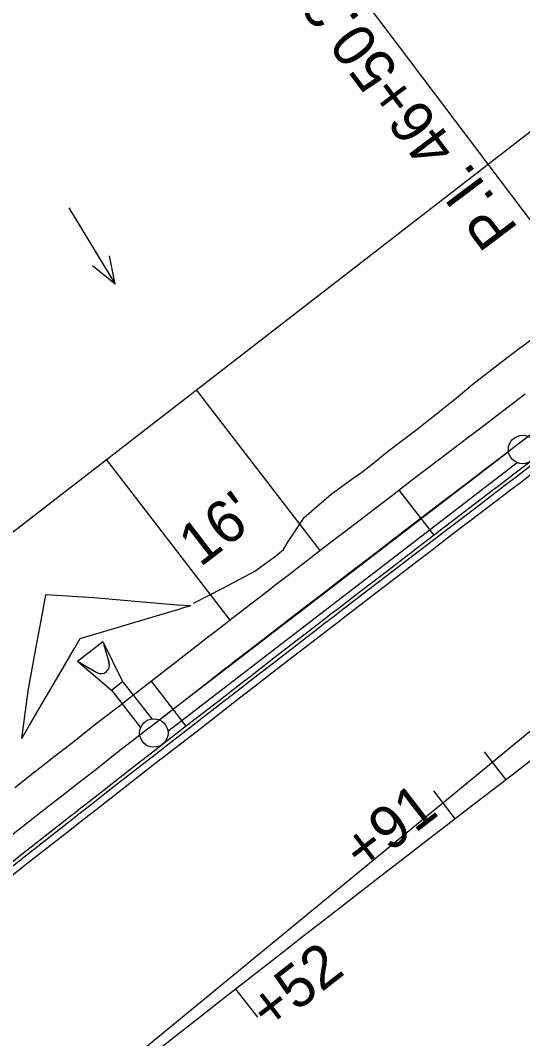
# Model space of a CAD drawing. Extents: x 1147550 to 1149124, y 2017436 to 2018779.
# Drawn here: x 1147906 to 1147976.6, y 2017760.9 to 2017904.1 of the extents above; entities that cross this region are included whole.
import ezdxf

# ---------------------------------------------------------------- set-up
doc = ezdxf.new("R2010")
doc.units = 0
for name, color, linetype in [('S_EDGE_CONCRETE', 7, 'Continuous'), ('S_HEADWALL', 7, 'Continuous'), ('S_MAILBOX', 7, 'Continuous'), ('S_RDW_PT_SYM', 7, 'Continuous'), ('S_SECONDARY_CTL', 7, 'Continuous'), ('S_TANK', 7, 'Continuous'), ('S_TELEPHONE_UTILITIES', 7, 'Continuous'), ('S_TELEPHONE_UTILITIES_ANNOT', 7, 'Continuous'), ('S_UTL_PT_SYM', 7, 'Continuous')]:
    doc.layers.add(name, color=color, linetype=linetype)

msp = doc.modelspace()

# ---------------------------------------------------------------- linework, layer by layer
at = {"layer": 'S_EDGE_CONCRETE'}
msp.add_line((1147825.51, 2017679.08), (1148011.14, 2017831.73), dxfattribs=at)
msp.add_lwpolyline([(1147971.17, 2017801.26), (1147974.22, 2017797.3)], dxfattribs=at)
msp.add_arc((1151464.82, 2013253.76), 5729.58, 124.62946, 129.43332, dxfattribs=at)
at = {"layer": 'S_HEADWALL'}
for p, q in [((1147930.68, 2017852.15), (1147948.09, 2017829.56)), ((1147918.03, 2017842.35), (1147935.42, 2017819.79)), ((1147959.2, 2017838.08), (1147964.09, 2017831.74)), ((1147924.35, 2017811.21), (1147929.24, 2017804.88)), ((1147964.04, 2017795.77), (1147967.09, 2017791.81)), ((1147939.36, 2017763.96), (1147936.28, 2017767.9))]:
    msp.add_line(p, q, dxfattribs=at)
at = {"layer": 'S_MAILBOX'}
msp.add_lwpolyline([(1147550.1, 2017525.89), (1147894.72, 2017801.4), (1147903.55, 2017831.14), (1148035.64, 2017933.4), (1148261.5, 2018084.85), (1148285.74, 2018084.65), (1148479.1, 2018223.18), (1148835.76, 2018573.62)], dxfattribs=at)
at = {"layer": 'S_RDW_PT_SYM'}
msp.add_lwpolyline([(1148011.14, 2017831.73), (1147938.86, 2017927.53)], dxfattribs=at)
at = {"layer": 'S_SECONDARY_CTL'}
for points in [[(1147930.31, 2017822.15), (1147934.44, 2017824.26), (1147938.95, 2017826.66), (1147939.76, 2017827.26), (1147941.84, 2017828.78), (1147941.85, 2017828.79), (1147942.97, 2017829.7), (1147943.5, 2017830.61), (1147945.85, 2017834.23), (1147949.68, 2017837.52), (1147952.55, 2017839.59), (1147952.62, 2017839.64), (1147953.77, 2017840.46), (1147954.97, 2017841.34), (1147957.74, 2017843.57), (1147961.75, 2017846.63), (1147964.48, 2017848.81), (1147964.61, 2017848.91), (1147965.69, 2017849.77), (1147967.24, 2017851.01), (1147969.59, 2017852.97), (1147973.59, 2017856.04), (1147976.33, 2017858.15), (1147976.51, 2017858.28), (1147977.59, 2017859.11)], [(1147906.18, 2017803.13), (1147906.55, 2017805.94), (1147907.11, 2017810.13), (1147908.34, 2017816.76), (1147909.22, 2017821.47), (1147909.23, 2017821.53), (1147909.57, 2017823.36), (1147909.58, 2017823.39), (1147916.29, 2017822.98), (1147923.16, 2017822.36), (1147928.01, 2017821.92), (1147928.1, 2017821.92), (1147929.94, 2017821.83)]]:
    msp.add_lwpolyline(points, dxfattribs=at)
at = {"layer": 'S_TANK'}
for p, q in [((1147912.8, 2017877.77), (1147919.31, 2017867.02)), ((1147919.31, 2017867.02), (1147918.52, 2017871.04)), ((1147919.31, 2017867.02), (1147916.12, 2017869.59))]:
    msp.add_line(p, q, dxfattribs=at)
at = {"layer": 'S_TELEPHONE_UTILITIES'}
for points in [[(1147905.17, 2017796.25), (1147907.97, 2017798.44), (1147908.05, 2017798.5), (1147908.72, 2017799.03), (1147909.13, 2017799.35), (1147910.72, 2017800.59), (1147913.1, 2017802.45), (1147917.07, 2017805.55), (1147919.9, 2017807.75), (1147919.93, 2017807.78), (1147921.03, 2017808.63), (1147921.05, 2017808.64), (1147925.02, 2017811.73), (1147929, 2017814.82), (1147931.82, 2017817), (1147931.87, 2017817.04), (1147932.98, 2017817.91), (1147933.36, 2017818.2), (1147936.97, 2017820.99), (1147940.96, 2017824.06), (1147941.75, 2017824.68), (1147943.79, 2017826.25), (1147943.8, 2017826.26), (1147944.95, 2017827.14), (1147945.72, 2017827.73), (1147948.94, 2017830.21), (1147952.93, 2017833.27), (1147955.74, 2017835.43), (1147955.81, 2017835.48), (1147956.93, 2017836.34), (1147958.1, 2017837.23), (1147960.93, 2017839.4), (1147964.93, 2017842.45), (1147967.71, 2017844.57), (1147967.84, 2017844.67), (1147968.94, 2017845.5), (1147970.51, 2017846.7), (1147972.95, 2017848.55), (1147976.96, 2017851.6)], [(1147904.29, 2017789.21), (1147908.25, 2017792.31), (1147911.05, 2017794.5), (1147911.13, 2017794.56), (1147911.81, 2017795.09), (1147912.22, 2017795.41), (1147913.8, 2017796.65), (1147916.18, 2017798.51), (1147920.15, 2017801.61), (1147922.97, 2017803.8), (1147923, 2017803.83), (1147924.1, 2017804.68), (1147924.12, 2017804.7), (1147928.09, 2017807.79), (1147932.07, 2017810.87), (1147934.88, 2017813.05), (1147934.93, 2017813.09), (1147936.04, 2017813.95), (1147936.42, 2017814.24), (1147940.03, 2017817.03), (1147944.01, 2017820.1), (1147944.81, 2017820.72), (1147946.84, 2017822.29), (1147946.85, 2017822.29), (1147947.99, 2017823.17), (1147948.77, 2017823.77), (1147951.98, 2017826.24), (1147955.98, 2017829.31), (1147958.78, 2017831.46), (1147958.85, 2017831.51), (1147959.97, 2017832.37), (1147961.14, 2017833.26), (1147963.97, 2017835.42), (1147967.97, 2017838.48), (1147970.74, 2017840.59), (1147970.87, 2017840.69), (1147971.97, 2017841.53), (1147973.54, 2017842.72), (1147975.97, 2017844.57), (1147979.98, 2017847.61)], [(1147902.19, 2017783.74), (1147906.15, 2017786.85), (1147910.1, 2017789.95), (1147912.9, 2017792.14), (1147912.98, 2017792.2), (1147913.65, 2017792.73), (1147914.06, 2017793.05), (1147915.65, 2017794.29), (1147918.03, 2017796.15), (1147921.99, 2017799.24), (1147924.81, 2017801.44), (1147924.85, 2017801.46), (1147925.94, 2017802.32), (1147925.96, 2017802.33), (1147929.93, 2017805.42), (1147933.9, 2017808.5), (1147936.72, 2017810.68), (1147936.77, 2017810.72), (1147937.88, 2017811.58), (1147938.26, 2017811.87), (1147941.86, 2017814.66), (1147945.84, 2017817.73), (1147946.64, 2017818.34), (1147948.67, 2017819.91), (1147948.68, 2017819.92), (1147949.82, 2017820.8), (1147950.6, 2017821.39), (1147953.81, 2017823.86), (1147957.8, 2017826.92), (1147960.61, 2017829.08), (1147960.67, 2017829.12), (1147961.79, 2017829.98), (1147962.97, 2017830.88), (1147965.79, 2017833.04), (1147969.79, 2017836.09), (1147972.56, 2017838.21), (1147972.69, 2017838.3), (1147973.79, 2017839.14), (1147975.36, 2017840.34), (1147977.79, 2017842.18)], [(1147902.5, 2017783.35), (1147906.46, 2017786.45), (1147910.41, 2017789.56), (1147913.21, 2017791.75), (1147913.29, 2017791.81), (1147913.96, 2017792.34), (1147914.37, 2017792.66), (1147915.96, 2017793.89), (1147918.33, 2017795.75), (1147922.3, 2017798.85), (1147925.12, 2017801.04), (1147925.15, 2017801.07), (1147926.25, 2017801.92), (1147926.27, 2017801.94), (1147930.24, 2017805.02), (1147934.21, 2017808.1), (1147937.02, 2017810.28), (1147937.07, 2017810.32), (1147938.19, 2017811.18), (1147938.56, 2017811.48), (1147942.16, 2017814.26), (1147946.15, 2017817.33), (1147946.94, 2017817.95), (1147948.98, 2017819.52), (1147948.99, 2017819.52), (1147950.13, 2017820.4), (1147950.9, 2017821), (1147954.12, 2017823.47), (1147958.11, 2017826.53), (1147960.91, 2017828.68), (1147960.98, 2017828.73), (1147962.1, 2017829.59), (1147963.27, 2017830.48), (1147966.09, 2017832.64), (1147970.09, 2017835.69), (1147972.86, 2017837.81), (1147972.99, 2017837.91), (1147974.09, 2017838.74), (1147975.66, 2017839.94), (1147978.09, 2017841.79)], [(1147903.12, 2017782.56), (1147907.07, 2017785.67), (1147911.03, 2017788.77), (1147913.83, 2017790.96), (1147913.9, 2017791.02), (1147914.58, 2017791.55), (1147914.99, 2017791.87), (1147916.57, 2017793.11), (1147918.95, 2017794.96), (1147922.91, 2017798.06), (1147925.73, 2017800.25), (1147925.77, 2017800.28), (1147926.86, 2017801.13), (1147926.88, 2017801.15), (1147930.85, 2017804.23), (1147934.82, 2017807.31), (1147937.63, 2017809.49), (1147937.69, 2017809.53), (1147938.8, 2017810.39), (1147939.18, 2017810.69), (1147942.78, 2017813.47), (1147946.76, 2017816.54), (1147947.55, 2017817.15), (1147949.59, 2017818.72), (1147949.6, 2017818.73), (1147950.74, 2017819.61), (1147951.51, 2017820.2), (1147954.73, 2017822.67), (1147958.71, 2017825.73), (1147961.52, 2017827.88), (1147961.58, 2017827.93), (1147962.7, 2017828.79), (1147963.88, 2017829.69), (1147966.7, 2017831.85), (1147970.7, 2017834.9), (1147973.47, 2017837.01), (1147973.6, 2017837.11), (1147974.69, 2017837.95), (1147976.27, 2017839.14), (1147978.7, 2017840.99)]]:
    msp.add_lwpolyline(points, dxfattribs=at)
at = {"layer": 'S_TELEPHONE_UTILITIES_ANNOT'}
for p, q in [((1147925.5, 2017805.76), (1147974.6, 2017843.51)), ((1147925.5, 2017805.76), (1147974.6, 2017843.51)), ((1147926.71, 2017804.17), (1147975.81, 2017841.93)), ((1147926.71, 2017804.17), (1147975.81, 2017841.93)), ((1147914.02, 2017813.99), (1147917.57, 2017816.76)), ((1147917.57, 2017816.76), (1147920.35, 2017811.15)), ((1147917.57, 2017816.76), (1147918.44, 2017813.72)), ((1147914.02, 2017813.99), (1147918.77, 2017809.93)), ((1147914.02, 2017813.99), (1147916.72, 2017812.42)), ((1147918.77, 2017809.93), (1147920.35, 2017811.15)), ((1147918.77, 2017809.93), (1147922.88, 2017804.66)), ((1147920.35, 2017811.15), (1147924.45, 2017805.89))]:
    msp.add_line(p, q, dxfattribs=at)
for centre in [(1147976.58, 2017843.78), (1147924.73, 2017803.91)]:
    msp.add_circle(centre, 2, dxfattribs=at)
msp.add_arc((1147917.31, 2017813.43), 1.17, 239.8428, 17.6763, dxfattribs=at)
at = {"layer": 'S_UTL_PT_SYM'}
msp.add_lwpolyline([(1147906.18, 2017803.13), (1147907.27, 2017805.01), (1147908.91, 2017807.82), (1147911.64, 2017812.52), (1147913.59, 2017815.85), (1147913.61, 2017815.89), (1147914.37, 2017817.19), (1147914.38, 2017817.21), (1147919.57, 2017818.76), (1147924.76, 2017820.3), (1147928.43, 2017821.38), (1147928.49, 2017821.4), (1147929.94, 2017821.83)], dxfattribs=at)

# ---------------------------------------------------------------- texts
at = {"layer": 'S_HEADWALL'}
for s, rotation, p in [("16'", 37.6235, (1147931.25, 2017827.14)), ('+91', 37.6235, (1147954.21, 2017784.16)), ('+52', 38.0135, (1147941.08, 2017761.75))]:
    msp.add_text(s, height=6, rotation=rotation, dxfattribs=at).set_placement(p)
at = {"layer": 'S_RDW_PT_SYM'}
msp.add_text('P.I. 46+50.35', height=6, rotation=127.0314, dxfattribs=at).set_placement((1147976.1, 2017874.85))

doc.saveas('drawing.dxf')
